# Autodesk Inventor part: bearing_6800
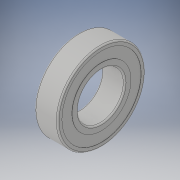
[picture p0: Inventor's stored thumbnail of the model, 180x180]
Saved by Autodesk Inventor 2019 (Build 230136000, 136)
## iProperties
Created: 2022-11
Part Number: bearing_6800
Material: Generic
Catalog Web Link: www.cadenas.de
Description: 6000_bearing-Deep Groove Ball Bearings
Vendor: MISUMI
Document SubType Name: Modeling
Designer: psAdmin
Manufacturer: MISUMI
Mass: 1.00952 g
Surface Area: 8.52846 cm^2
Volume: 1.00952 cm^3
Density: 1 g/cm^3
Appearance: PSOLRGB-175-175-175
Category: PARTsolutions
Company: MISUMI
Title: bearing_6800
Author: Cadenas PARTsolutions
Comments: Deep Groove Ball Bearings
PSOL_IDENT_0: {$CADENAS_DATA/23d-libs/misumi/metric/accessories/bearing_6000.prj},170 {VTYP=3D},{NB=bearing_6800},
PSOL_IDENT_1: {LINA=bearing_6800},{NN=6000_bearing},{DATE=30.06.2021 13:30:08},{GEOMDATE=24.10.2013 00:00:00},{VER
PSOL_IDENT_2: SION=},{LINEID=20},{WBVAR=},{WBNUMERIC=}  {NB=bearing_6800},{LINA=bearing_6800},{KT=DUMMY},{PN=beari
PSOL_IDENT_3: ng_6800},{BN=6800},{DD=10},{D=19},{B=5},{RR=0.3},{DSMIN=12.0},{DS1=12.50},{DSMAX=12.50},{DDHH=17.0},
PSOL_IDENT_4: {R=0.3},{R1=1.000},{R2=1.000},{MASS=5},{MASS11=5},{AA=4.8850},{BB=0.9250},{CC=1.3700},{DD1=1.000}
NB: bearing_6800
NN: 6000_bearing
NT: Deep Groove Ball Bearings
NBSYN: $PN.
LINA: bearing_6800
CATALOG: Misumi
PN: bearing_6800
BN: 6800
DD: 10
D: 19
B: 5
RR: 0.3
DSMIN: 12
DDHH: 17
R: 0.3
MASS11: 5
SUPPLIER: MISUMI
ARTICLENO: bearing_6800
BOMINFO: bearing_6800
CREATOR: CADENAS GmbH
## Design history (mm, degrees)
sketch "Sketch_1"
  geometry: L1 (5, 0)-(0, 0); L2 (0.3, 5)-(4.7, 5); L3 (5, 5.3)-(5, 6.37); L4 (5, 6.37)-(4.942, 6.37); L5 (4.942, 6.37)-(4.942, 8.575); L6 (4.942, 8.575)-(5, 8.575); L7 (5, 8.575)-(5, 9.2); L8 (4.7, 9.5)-(0.3, 9.5); L9 (0, 9.2)-(0, 8.575); L10 (0, 8.575)-(0.058, 8.575); L11 (0.058, 8.575)-(0.058, 6.37); L12 (0.058, 6.37)-(0, 6.37); L13 (0, 6.37)-(0, 5.3); A1 r 0.3 centre (0.3, 5.3) between (0, 5.3) and (0.3, 5); A2 r 0.3 centre (4.7, 5.3) between (4.7, 5) and (5, 5.3); A3 r 0.3 centre (4.7, 9.2) between (5, 9.2) and (4.7, 9.5); A4 r 0.3 centre (0.3, 9.2) between (0.3, 9.5) and (0, 9.2)
  constraints: 26 end point, 8 point on circle, 4 centre point
revolve "Revolution1" sketch "Sketch_1" stored, may be unused: angle "d0" = 360 deg
node "center_point_XY"
node "center_point_YZ"
node "center_point_ZX"
node "center_point_X"
node "center_point_Y"
node "center_point_Z"
node "center_point_Center"
node "to_housing_XY"
node "to_housing_YZ"
node "to_housing_ZX"
node "to_housing_X"
node "to_housing_Y"
node "to_housing_Z"
node "to_housing_Center"
node "to_ring_XY"
node "to_ring_YZ"
node "to_ring_ZX"
node "to_ring_X"
node "to_ring_Y"
node "to_ring_Z"
node "to_ring_Center"
body "Solid1"
other parameters: "d1" = 0
